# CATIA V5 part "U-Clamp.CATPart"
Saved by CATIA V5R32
Part number: U-Clamp
Bounding box of the stored display mesh (mm): x -22.987 to 22.987, y -6.35 to 6.35, z -25.4 to 28.702
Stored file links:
  D:\PROJECTS\Project 2022\CATIA V5 6R 2022\Resources\Part Files\c13_catia_v5_6r2022_prt\c13_catia_v5-6r2022_figr_13-45\Part & Asm files\U-Clamp.CATPart
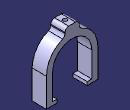
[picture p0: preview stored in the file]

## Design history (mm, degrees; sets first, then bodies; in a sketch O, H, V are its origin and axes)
Body1 (main body)
  Sketch1 on zx-plane, origin (0, 0, 0), H (-1, 0, 0), V (0, 0, 1)
    arc A1 centre (0, 0) radius 17.526 from (17.526, 0) to (-17.526, 0) ccw
    point P1 (-17.526, 0)
    point P2 (17.526, 0)
    line L1 (-17.526, 0) -> (-17.526, -22.352)
    point P3 (-17.526, -22.352)
    line L2 (-17.526, -22.352) -> (-13.462, -22.352)
    point P4 (-13.462, -22.352)
    line L3 (-13.462, -22.352) -> (-13.462, -25.4)
    point P5 (-13.462, -25.4)
    line L4 (-13.462, -25.4) -> (-22.987, -25.4)
    point P6 (-22.987, -25.4)
    line L5 (-22.987, -25.4) -> (-22.987, 0)
    point P7 (-22.987, 0)
    arc A2 centre (0, 0) radius 22.987 from (-22.987, 0) to (-6.35, 22.0925) cw
    point P9 (22.987, 0)
    point P10 (22.987, 0)
    point P11 (22.987, -25.4)
    line L6 (22.987, -25.4) -> (22.987, 0)
    point P12 (13.462, -25.4)
    line L7 (13.462, -25.4) -> (22.987, -25.4)
    point P13 (13.462, -22.352)
    line L8 (13.462, -22.352) -> (13.462, -25.4)
    point P14 (17.526, -22.352)
    line L9 (17.526, -22.352) -> (13.462, -22.352)
    point P15 (17.526, 0)
    line L10 (17.526, 0) -> (17.526, -22.352)
    line L11 (-6.35, 22.0925) -> (-6.35, 28.702)
    point P16 (-6.35, 28.702)
    line L12 (-6.35, 28.702) -> (6.35, 28.702)
    point P17 (6.35, 28.702)
    line L13 (6.35, 28.702) -> (6.35, 22.0925)
    point P18 (6.35, 22.0925)
    arc A3 centre (0, 0) radius 22.987 from (6.35, 22.0925) to (22.987, 0) cw
    radius A1 = 17.526
    distance L3 V = 13.462
    distance H L2 = 22.352
    distance H L4 = 25.4
    distance V L5 = 22.987
    distance P16 P17 = 12.7
    distance L11 V = 6.35
    distance L12 H = 28.702
    coincidence: P1 H, P2 H, P7 H, A2 P18, A2 A3, P2 P15, P9 P10
    tangency: L1 A1, A2 L5
    horizontal: L2 H, L4 H, L12 H
    vertical: L3 V, L5 V, L11 V, L13 V
    concentricity: A2 A1
    symmetry: P7 P10 V, P6 P11 V, L5 L6 V, P5 P12 V, L4 L7 V, P4 P13 V, L3 L8 V, P3 P14 V, L2 L9 V, P1 P15 V, L1 L10 V
  Pad1: profile Sketch1, direction (0, -1, 0), length 6.35, mirrored extent
  Fillet1: radius 3.302, on 4 edges
  Sketch2 on face of Pad1, origin (-0.057, 2.6412, 28.702), H (1, 0, 0), V (0, 1, 0)
    point P1 (0.057, -2.6412)
    reference intersected line E1 through (0.057, 0) direction (0, 1) from yz-plane
    reference intersected line E2 through (0, -2.6412) direction (-1, 0) from zx-plane
    coincidence: E1 P1, E2 P1
  Hole1: placed by Sketch2, at (0, 0, 28.702) direction (0, 0, -1), diameter 3.81, depth 25.4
